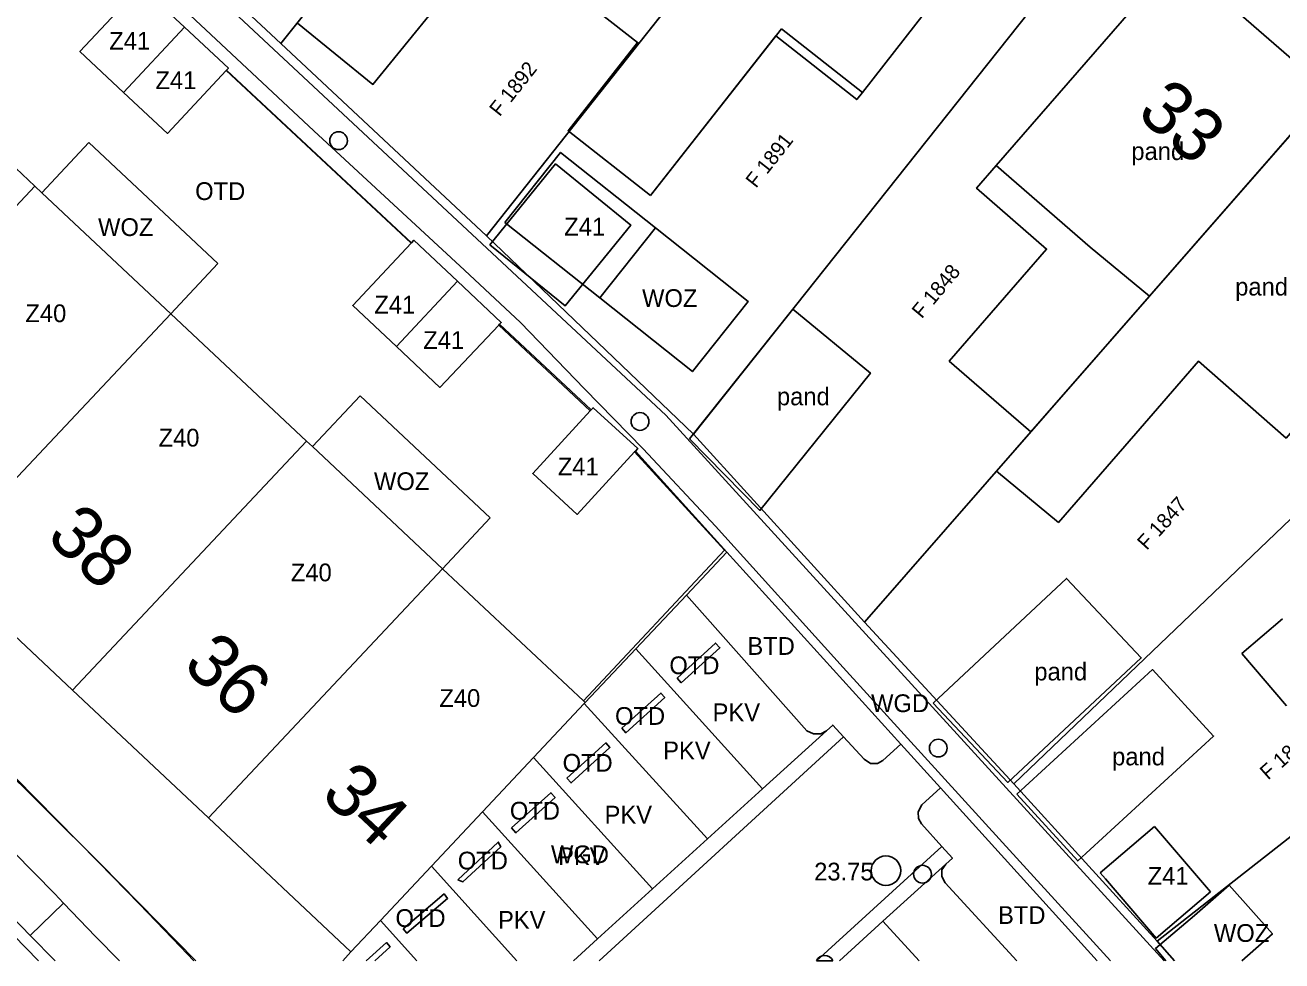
# Model space of a CAD drawing. Extents: x 198240 to 198429, y 356553 to 356721.
# Drawn here: x 198284.19 to 198326.68, y 356553.7 to 356585.33 of the extents above; entities that cross this region are included whole.
import ezdxf

# ---------------------------------------------------------------- set-up
doc = ezdxf.new("R2010")
doc.units = 0
for name, color, linetype in [('(presentatie) Code GPNDDECOM (lijn of vlak) (zonder attributen) niet in de presentatietabel', 7, 'Continuous'), ('begroeid terreindeel kenmerkpunt', 7, 'Continuous'), ('bijgebouw', 7, 'Continuous'), ('grens individueel parkeervak', 7, 'Continuous'), ('Grens maaiveld', 7, 'Continuous'), ('grens WOZ object', 7, 'Continuous'), ('hoofdgebouw', 7, 'Continuous'), ('Hoogtepunt', 7, 'Continuous'), ('huisnummerreeks BGT', 7, 'Continuous'), ('identificerend kenmerkpunt bijpand', 7, 'Continuous'), ('identificerend kenmerkpunt pand', 7, 'Continuous'), ('identificerend kenmerkpunt parkeervak', 7, 'Continuous'), ('identificerend kenmerkpunt WOZ object', 7, 'Continuous'), ('Inspectieput_rioolput', 7, 'Continuous'), ('kant verharding', 7, 'Continuous'), ('kolk', 7, 'Continuous'), ('onbegroeid terreindeel kenmerkpunt', 7, 'Continuous'), ('Perceelnummer', 7, 'Continuous'), ('perceelsgrens_definitief', 7, 'Continuous'), ('schutting geen IMGeo', 7, 'Continuous'), ('tussenmuur', 7, 'Continuous'), ('tussenmuur bijgebouw (GBKN Zuid)', 7, 'Continuous'), ('wegdeel kenmerkpunt', 7, 'Continuous')]:
    doc.layers.add(name, color=color, linetype=linetype)

msp = doc.modelspace()

# ---------------------------------------------------------------- linework, layer by layer
at = {"layer": '(presentatie) Code GPNDDECOM (lijn of vlak) (zonder attributen) niet in de presentatietabel'}
for p, q in [((198305.334, 356579.571), (198309.759, 356585.206)), ((198312.495, 356583.057), (198309.759, 356585.206)), ((198317.022, 356580.581), (198320.195, 356577.825)), ((198303.618, 356576.108), (198300.409, 356578.657)), ((198322.202, 356576.169), (198320.195, 356577.825)), ((198322.202, 356576.169), (198317.034, 356570.258))]:
    msp.add_line(p, q, dxfattribs=at)
msp.add_lwpolyline([(198305.501, 356578.478), (198302.292, 356581.027), (198300.409, 356578.657)], dxfattribs=at)
at = {"layer": 'bijgebouw'}
for p, q in [((198290.985, 356583.793), (198291, 356583.809)), ((198297.257, 356577.972), (198297.241, 356577.955)), ((198300.204, 356575.194), (198300.228, 356575.219)), ((198303.328, 356572.328), (198303.297, 356572.294)), ((198304.797, 356570.903), (198304.824, 356570.933)), ((198322.369, 356558.246), (198320.535, 356556.68)), ((198324.259, 356556.032), (198322.369, 356558.246)), ((198320.535, 356556.68), (198320.71, 356556.475)), ((198320.71, 356556.475), (198322.425, 356554.465)), ((198322.425, 356554.465), (198324.259, 356556.032))]:
    msp.add_line(p, q, dxfattribs=at)
for points in [[(198293.396, 356585.4), (198295.948, 356583.327), (198299.176, 356587.3), (198296.591, 356589.4)], [(198304.895, 356584.747), (198302.686, 356586.482), (198305.057, 356589.501)], [(198304.895, 356584.747), (198304.94, 356584.712), (198307.038, 356587.361)], [(198288.004, 356586.53), (198286.046, 356584.433), (198287.524, 356583.052)], [(198289.586, 356585.259), (198288.107, 356586.64), (198288.036, 356586.564)], [(198291, 356583.809), (198291.064, 356583.878), (198289.586, 356585.259)], [(198287.524, 356583.052), (198289.003, 356581.671), (198290.985, 356583.793)], [(198297.241, 356577.955), (198295.268, 356575.857), (198296.743, 356574.47)], [(198298.812, 356576.67), (198297.337, 356578.057), (198297.257, 356577.972)], [(198300.228, 356575.219), (198300.287, 356575.282), (198298.812, 356576.67)], [(198310.142, 356575.73), (198312.766, 356573.569), (198309.03, 356568.929), (198306.657, 356571.345)], [(198296.743, 356574.47), (198298.218, 356573.082), (198300.204, 356575.194)], [(198303.297, 356572.294), (198301.352, 356570.172), (198302.86, 356568.79), (198304.797, 356570.903)], [(198304.824, 356570.933), (198304.9, 356571.016), (198303.392, 356572.398), (198303.328, 356572.328)], [(198314.887, 356562.417), (198317.418, 356559.735), (198321.923, 356563.944), (198319.392, 356566.626), (198314.887, 356562.417)], [(198317.712, 356559.331), (198319.777, 356557.081), (198324.37, 356561.297), (198322.305, 356563.547), (198317.712, 356559.331)]]:
    msp.add_lwpolyline(points, dxfattribs=at)
at = {"layer": 'grens individueel parkeervak'}
for p, q in [((198304.837, 356564.248), (198309.124, 356559.515)), ((198303.097, 356562.401), (198301.379, 356560.573)), ((198303.097, 356562.401), (198303.124, 356562.43)), ((198303.097, 356562.401), (198307.264, 356557.825)), ((198309.124, 356559.515), (198311.28, 356561.474)), ((198301.379, 356560.573), (198299.658, 356558.742)), ((198301.379, 356560.573), (198305.402, 356556.133)), ((198307.264, 356557.825), (198309.124, 356559.515)), ((198299.658, 356558.742), (198297.929, 356556.901)), ((198299.658, 356558.742), (198303.54, 356554.441)), ((198305.402, 356556.133), (198307.264, 356557.825)), ((198297.929, 356556.901), (198296.206, 356555.068)), ((198297.929, 356556.901), (198300.812, 356553.702)), ((198303.54, 356554.441), (198305.402, 356556.133)), ((198284.368, 356554.558), (198285.496, 356555.657)), ((198296.206, 356555.068), (198295.207, 356554.005)), ((198297.434, 356553.702), (198296.206, 356555.068)), ((198313.191, 356555.041), (198314.41, 356553.702)), ((198302.726, 356553.702), (198303.54, 356554.441))]:
    msp.add_line(p, q, dxfattribs=at)
at = {"layer": 'Grens maaiveld'}
for p, q in [((198318.19, 356571.58), (198322.202, 356576.169)), ((198318.19, 356571.58), (198317.034, 356570.258)), ((198306.55, 356566.066), (198307.918, 356567.518)), ((198311.859, 356561.274), (198303.599, 356553.702))]:
    msp.add_line(p, q, dxfattribs=at)
for points in [[(198313.331, 356595.307), (198318.74, 356591.044), (198314.299, 356585.364), (198312.495, 356583.057)], [(198328.26, 356583.099), (198323.101, 356587.58), (198317.022, 356580.581)], [(198305.334, 356579.571), (198302.548, 356581.759), (198304.895, 356584.747)], [(198312.495, 356583.057), (198312.305, 356582.814), (198309.569, 356584.963), (198305.334, 356579.571)], [(198299.904, 356577.904), (198302.124, 356580.636), (198304.667, 356578.57), (198302.448, 356575.838), (198299.904, 356577.904)], [(198318.19, 356571.58), (198316.276, 356573.243), (198315.433, 356573.975), (198318.72, 356577.76), (198316.356, 356579.814), (198317.022, 356580.581)], [(198284.644, 356553.702), (198283.387, 356555), (198281.872, 356556.493), (198280.238, 356558.141), (198278.516, 356559.778), (198276.797, 356561.449), (198275.184, 356562.933), (198273.567, 356564.419), (198272.007, 356565.849), (198272.129, 356565.996)], [(198311.859, 356561.274), (198311.494, 356561.673), (198311.28, 356561.474)], [(198311.859, 356561.274), (198312.554, 356560.515), (198312.774, 356560.376), (198313.006, 356560.376), (198313.187, 356560.478), (198313.798, 356561.028)], [(198315.186, 356557.571), (198310.94, 356553.702)]]:
    msp.add_lwpolyline(points, dxfattribs=at)
at = {"layer": 'grens WOZ object'}
for p, q in [((198284.761, 356579.664), (198286.347, 356581.358)), ((198290.707, 356577.276), (198286.347, 356581.358)), ((198305.501, 356578.478), (198303.618, 356576.108)), ((198290.707, 356577.276), (198289.116, 356575.577)), ((198295.517, 356572.803), (198293.903, 356571.084)), ((198299.918, 356568.674), (198295.517, 356572.803)), ((198298.304, 356566.954), (198299.918, 356568.674)), ((198325.32, 356564.087), (198326.702, 356565.264)), ((198326.828, 356562.317), (198325.32, 356564.087))]:
    msp.add_line(p, q, dxfattribs=at)
for points in [[(198305.501, 356578.478), (198308.634, 356575.989), (198306.752, 356573.619), (198303.618, 356576.108)], [(198325.322, 356553.702), (198326.359, 356554.614), (198324.889, 356556.264), (198323.723, 356555.237)], [(198323.723, 356555.237), (198322.403, 356554.118), (198322.756, 356553.702)]]:
    msp.add_lwpolyline(points, dxfattribs=at)
at = {"layer": 'hoofdgebouw'}
for p, q in [((198284.522, 356579.888), (198279.929, 356584.199)), ((198284.761, 356579.664), (198284.522, 356579.888)), ((198289.116, 356575.577), (198284.761, 356579.664)), ((198293.71, 356571.265), (198289.116, 356575.577)), ((198293.903, 356571.084), (198293.71, 356571.265)), ((198298.304, 356566.954), (198293.903, 356571.084)), ((198281.207, 356567.165), (198285.798, 356562.85)), ((198303.064, 356562.486), (198298.304, 356566.954)), ((198285.798, 356562.85), (198290.388, 356558.535)), ((198303.124, 356562.43), (198303.064, 356562.486)), ((198301.379, 356560.573), (198303.097, 356562.401)), ((198303.097, 356562.401), (198303.124, 356562.43)), ((198299.658, 356558.742), (198301.379, 356560.573)), ((198297.929, 356556.901), (198299.658, 356558.742)), ((198290.388, 356558.535), (198295.207, 356554.005)), ((198296.206, 356555.068), (198297.929, 356556.901)), ((198295.207, 356554.005), (198296.206, 356555.068))]:
    msp.add_line(p, q, dxfattribs=at)
for points in [[(198328.26, 356583.099), (198333.365, 356578.665), (198328.634, 356573.26), (198328.544, 356573.339), (198326.816, 356571.37), (198323.857, 356573.967), (198321.738, 356571.528)], [(198321.738, 356571.528), (198319.124, 356568.519), (198317.034, 356570.258)]]:
    msp.add_lwpolyline(points, dxfattribs=at)
at = {"layer": 'Inspectieput_rioolput'}
msp.add_circle((198313.293, 356556.751), 0.5, dxfattribs=at)
at = {"layer": 'kant verharding'}
for p, q in [((198297.257, 356577.972), (198291, 356583.809)), ((198303.328, 356572.328), (198300.228, 356575.219)), ((198307.918, 356567.518), (198304.824, 356570.933)), ((198313.798, 356561.028), (198307.918, 356567.518)), ((198304.837, 356564.248), (198306.55, 356566.066)), ((198303.124, 356562.43), (198304.837, 356564.248)), ((198315.135, 356559.552), (198313.798, 356561.028)), ((198320.434, 356553.702), (198315.135, 356559.552)), ((198313.191, 356555.041), (198315.313, 356556.975)), ((198311.722, 356553.702), (198313.191, 356555.041))]:
    msp.add_line(p, q, dxfattribs=at)
for points in [[(198322.703, 356553.702), (198305.854, 356572.145), (198276.632, 356599.402)], [(198259.936, 356581.349), (198263.162, 356578.714), (198264.691, 356577.443), (198266.216, 356576.128), (198267.724, 356574.825), (198269.227, 356573.509), (198270.721, 356572.194), (198272.197, 356570.855), (198273.693, 356569.495), (198275.162, 356568.148), (198276.635, 356566.799), (198278.09, 356565.437), (198279.565, 356564.071), (198280.999, 356562.677), (198282.453, 356561.301), (198283.864, 356559.891), (198285.266, 356558.474), (198286.669, 356557.036), (198288.064, 356555.615), (198289.442, 356554.173), (198289.902, 356553.702)], [(198306.55, 356566.066), (198310.62, 356561.476), (198310.841, 356561.371), (198311.097, 356561.372), (198311.28, 356561.474)], [(198306.238, 356563.254), (198306.372, 356563.101), (198307.681, 356564.283), (198307.532, 356564.441), (198306.238, 356563.254)], [(198304.362, 356561.562), (198304.498, 356561.413), (198305.816, 356562.603), (198305.686, 356562.752), (198304.362, 356561.562)], [(198302.501, 356559.882), (198302.648, 356559.718), (198303.963, 356560.918), (198303.825, 356561.067), (198302.501, 356559.882)], [(198315.135, 356559.552), (198314.507, 356558.973), (198314.378, 356558.744), (198314.388, 356558.513), (198314.496, 356558.338), (198315.186, 356557.571)], [(198281.695, 356559.467), (198282.364, 356558.797), (198283.801, 356557.392), (198285.2, 356555.966), (198285.496, 356555.657)], [(198300.638, 356558.199), (198300.782, 356558.029), (198302.106, 356559.227), (198301.969, 356559.382), (198300.638, 356558.199)], [(198280.588, 356558.36), (198281.178, 356557.775), (198282.686, 356556.26), (198284.072, 356554.859), (198284.368, 356554.558)], [(198298.817, 356556.437), (198298.994, 356556.371), (198300.271, 356557.556), (198300.188, 356557.715), (198298.817, 356556.437)], [(198315.186, 356557.571), (198315.54, 356557.177), (198315.313, 356556.975)], [(198315.313, 356556.975), (198315.181, 356556.781), (198315.177, 356556.548), (198315.29, 356556.337), (198317.717, 356553.702)], [(198296.968, 356554.779), (198297.102, 356554.635), (198298.476, 356555.813), (198298.357, 356555.964), (198296.968, 356554.779)], [(198285.496, 356555.657), (198286.577, 356554.53), (198287.381, 356553.702)], [(198284.368, 356554.558), (198285.21, 356553.702)], [(198294.928, 356553.702), (198295.207, 356554.005)], [(198296.013, 356553.702), (198296.529, 356554.177), (198296.405, 356554.318), (198295.726, 356553.702)]]:
    msp.add_lwpolyline(points, dxfattribs=at)
at = {"layer": 'kolk'}
msp.add_line((198310.944, 356553.702), (198311.496, 356553.702), dxfattribs=at)
for centre in [(198294.79, 356581.424), (198304.978, 356571.933), (198315.062, 356560.893), (198314.528, 356556.631)]:
    msp.add_circle(centre, 0.3, dxfattribs=at)
msp.add_arc((198311.22, 356553.583), 0.3, 23.282, 156.718, dxfattribs=at)
at = {"layer": 'perceelsgrens_definitief'}
for points in [[(198292.841, 356584.705), (198307.969, 356603.645)], [(198275.847, 356598.687), (198293.958, 356581.762), (198299.047, 356577.045), (198300.934, 356575.281), (198303.1, 356573.036), (198305.083, 356571.014), (198307.527, 356568.392), (198311.848, 356563.616), (198317.236, 356557.707), (198320.88, 356553.702)], [(198299.785, 356578.205), (198315.332, 356597.833)], [(198306.788, 356571.509), (198322.937, 356591.83)], [(198285.695, 356591.384), (198292.841, 356584.705)], [(198312.565, 356565.146), (198330.567, 356585.738)], [(198292.841, 356584.705), (198299.785, 356578.205)], [(198289.969, 356553.702), (198286.746, 356556.976), (198283.098, 356560.585), (198279.403, 356564.145), (198275.66, 356567.655), (198271.871, 356571.116), (198268.036, 356574.525), (198264.156, 356577.884), (198260.232, 356581.19)], [(198317.612, 356559.68), (198337.623, 356578.829)], [(198299.785, 356578.205), (198306.788, 356571.509)], [(198306.788, 356571.509), (198312.565, 356565.146)], [(198322.461, 356554.365), (198343.976, 356571.222)], [(198312.565, 356565.146), (198317.612, 356559.68)], [(198317.612, 356559.68), (198322.461, 356554.365)], [(198322.461, 356554.365), (198323.049, 356553.702)]]:
    msp.add_lwpolyline(points, dxfattribs=at)
at = {"layer": 'schutting geen IMGeo'}
for p, q in [((198297.241, 356577.955), (198290.985, 356583.793)), ((198303.297, 356572.294), (198300.204, 356575.194))]:
    msp.add_line(p, q, dxfattribs=at)
msp.add_lwpolyline([(198304.797, 356570.903), (198307.839, 356567.583), (198303.064, 356562.486)], dxfattribs=at)
at = {"layer": 'tussenmuur'}
for p, q in [((198322.202, 356576.169), (198328.26, 356583.099)), ((198276.617, 356571.48), (198284.522, 356579.888)), ((198281.207, 356567.165), (198289.116, 356575.577)), ((198285.798, 356562.85), (198293.71, 356571.265)), ((198298.304, 356566.954), (198290.388, 356558.535))]:
    msp.add_line(p, q, dxfattribs=at)
at = {"layer": 'tussenmuur bijgebouw (GBKN Zuid)'}
for p, q in [((198289.586, 356585.259), (198287.524, 356583.052)), ((198298.812, 356576.67), (198296.743, 356574.47)), ((198306.657, 356571.345), (198310.142, 356575.73))]:
    msp.add_line(p, q, dxfattribs=at)

# ---------------------------------------------------------------- texts
at = {"layer": 'begroeid terreindeel kenmerkpunt'}
for p in [(198308.608, 356564.045), (198317.082, 356554.95)]:
    msp.add_text('BTD', height=0.6, dxfattribs=at).set_placement(p)
at = {"layer": 'Hoogtepunt'}
msp.add_text('23.75', height=0.6, dxfattribs=at).set_placement((198310.866, 356556.419))
msp.add_text('23.75', height=0.6, dxfattribs=at).set_placement((198310.866, 356556.419))
at = {"layer": 'huisnummerreeks BGT'}
for s, rotation, p in [('33', 319, (198321.723, 356582.287)), ('38', 316.8, (198284.865, 356567.98)), ('36', 316.8, (198289.477, 356563.645)), ('34', 316.8, (198294.139, 356559.262))]:
    msp.add_text(s, height=1.8, rotation=rotation, dxfattribs=at).set_placement(p)
at = {"layer": 'identificerend kenmerkpunt bijpand'}
for s, p in [('Z41', (198287.037, 356584.499)), ('Z41', (198288.599, 356583.166)), ('Z41', (198302.416, 356578.218)), ('Z41', (198295.997, 356575.58)), ('Z41', (198297.651, 356574.385)), ('pand', (198309.608, 356572.48)), ('Z41', (198302.199, 356570.109)), ('pand', (198318.308, 356563.18)), ('pand', (198320.938, 356560.31)), ('Z41', (198322.141, 356556.275))]:
    msp.add_text(s, height=0.6, dxfattribs=at).set_placement(p)
at = {"layer": 'identificerend kenmerkpunt pand'}
for s, p in [('pand', (198321.588, 356580.77)), ('pand', (198325.098, 356576.19)), ('Z40', (198284.203, 356575.29)), ('Z40', (198288.705, 356571.085)), ('Z40', (198293.176, 356566.531)), ('Z40', (198298.197, 356562.285))]:
    msp.add_text(s, height=0.6, dxfattribs=at).set_placement(p)
at = {"layer": 'identificerend kenmerkpunt parkeervak'}
for p in [(198307.433, 356561.801), (198305.762, 356560.515), (198303.781, 356558.344), (198302.21, 356556.937), (198300.179, 356554.788)]:
    msp.add_text('PKV', height=0.6, dxfattribs=at).set_placement(p)
at = {"layer": 'identificerend kenmerkpunt WOZ object'}
for p in [(198286.659, 356578.202), (198305.048, 356575.804), (198295.985, 356569.614), (198324.378, 356554.343)]:
    msp.add_text('WOZ', height=0.6, dxfattribs=at).set_placement(p)
at = {"layer": 'onbegroeid terreindeel kenmerkpunt'}
for p in [(198289.942, 356579.419), (198305.971, 356563.392), (198304.134, 356561.679), (198302.362, 356560.096), (198300.58, 356558.476), (198298.819, 356556.791), (198296.713, 356554.848)]:
    msp.add_text('OTD', height=0.6, dxfattribs=at).set_placement(p)
at = {"layer": 'Perceelnummer'}
for s, rotation, p in [('F 1892', 51.6, (198300.235, 356582.214)), ('F 1891', 51.8, (198308.901, 356579.794)), ('F 1848', 50.2, (198314.506, 356575.383)), ('F 1847', 47.8, (198322.109, 356567.558)), ('F 1846', 41.4, (198326.208, 356559.795))]:
    msp.add_text(s, height=0.5, rotation=rotation, dxfattribs=at).set_placement(p)
at = {"layer": 'wegdeel kenmerkpunt'}
for p in [(198312.789, 356562.109), (198301.969, 356557.002)]:
    msp.add_text('WGD', height=0.6, dxfattribs=at).set_placement(p)

doc.saveas('drawing.dxf')
